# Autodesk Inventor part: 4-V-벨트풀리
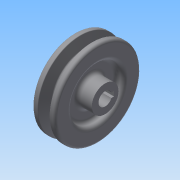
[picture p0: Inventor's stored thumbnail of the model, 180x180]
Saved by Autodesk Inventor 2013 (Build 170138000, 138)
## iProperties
Created: 2015-02
Part Number: 4-V-벨트풀리
Material: 일반
Document SubType Name: Modeling
Designer: Administrator
Density: 1 g/cm^3
Author: Administrator
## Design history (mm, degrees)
sketch "스케치1"
  geometry: L1 (0, 0)-(25, 0); L2 (25, 5.5)-(25, 11); L3 (25, 11)-(13, 11); L4 (13, 11)-(13, 21.5); L5 (13, 21.5)-(19, 21.5); L6 (19, 21.5)-(19, 35.2); L7 (19, 35.2)-(14.325, 35.2); L8 (14.325, 35.2)-(11.574, 26.2); L9 (11.574, 26.2)-(7.426, 26.2); L10 (7.426, 26.2)-(4.675, 35.2); L11 (4.675, 35.2)-(0, 35.2); L12 (0, 35.2)-(0, 21.5); L13 (0, 21.5)-(6, 21.5); L14 (6, 21.5)-(6, 11); L15 (6, 11)-(0, 11); L16 (0, 11)-(0, 5.5); L17 (0, 5.5)-(25, 5.5); 2 further points
  constraints: 34 end point, 8 horizontal, 4 collinear, 4 vertical, 3 equal length, 2 perpendicular, 2 point on line, 2 vertical alignment, 1 horizontal alignment, 1 parallel
  dimensions: "d0" = 25 distance of L1.start L1.end; "d1" = 8 distance of point (13.5, 32.5) point (5.5, 32.5); "d2" = 34 deg angle of L8 L10; "d3" = 6.3 vertical distance of L8.end point (13.5, 32.5); "d4" = 2.7 distance from line of point (13.5, 32.5) L7; "d5" = 19 distance between parallel lines of L6 L12; "d6" = 6 distance of L12.end L13.end; "d7" = 11 diameter of L17 L1; "d8" = 22 diameter of L3 L1; "d9" = 43 diameter of L5 L1; "d10" = 65 diameter of point (13.5, 32.5) L1
revolve "회전1" sketch "스케치1" stored, may be unused: angle "d11" = 90 deg
sketch "스케치2"
  geometry: L1 (-2, 5.123)-(-2, 7.3); L2 (-2, 7.3)-(2, 7.3); L3 (2, 7.3)-(2, 5.123); A1 r 5.5 centre (0, 0) between (-2, 5.123) and (2, 5.123) reference; 1 further point
  constraints: 6 end point, 2 point on circle, 2 vertical, 1 midpoint, 1 perpendicular, 1 vertical alignment
  dimensions: "d12" = 12.8 dimension on A1 L2; "d13" = 4 distance of L1.end L2.end
extrude "돌출1" cut sketch "스케치2" stored distance "d14" = 10; taper "d15" = 0 deg
fillet "모깎기1" dims "d16" = 1, "d17" = 0.5, "d18" = 2
fillet "모깎기2" dims "d19" = 3
node "솔리드1"
